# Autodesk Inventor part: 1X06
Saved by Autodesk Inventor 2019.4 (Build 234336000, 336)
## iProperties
Created: 2020-01
Part Number: 1X06
Material: Generic
Document SubType Name: Modeling
Designer: Administrator
Density: 1 g/cm^3
Appearance: Default
Title: 1X06
Author: Administrator
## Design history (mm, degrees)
feature "1X06"
body "Solid1"
